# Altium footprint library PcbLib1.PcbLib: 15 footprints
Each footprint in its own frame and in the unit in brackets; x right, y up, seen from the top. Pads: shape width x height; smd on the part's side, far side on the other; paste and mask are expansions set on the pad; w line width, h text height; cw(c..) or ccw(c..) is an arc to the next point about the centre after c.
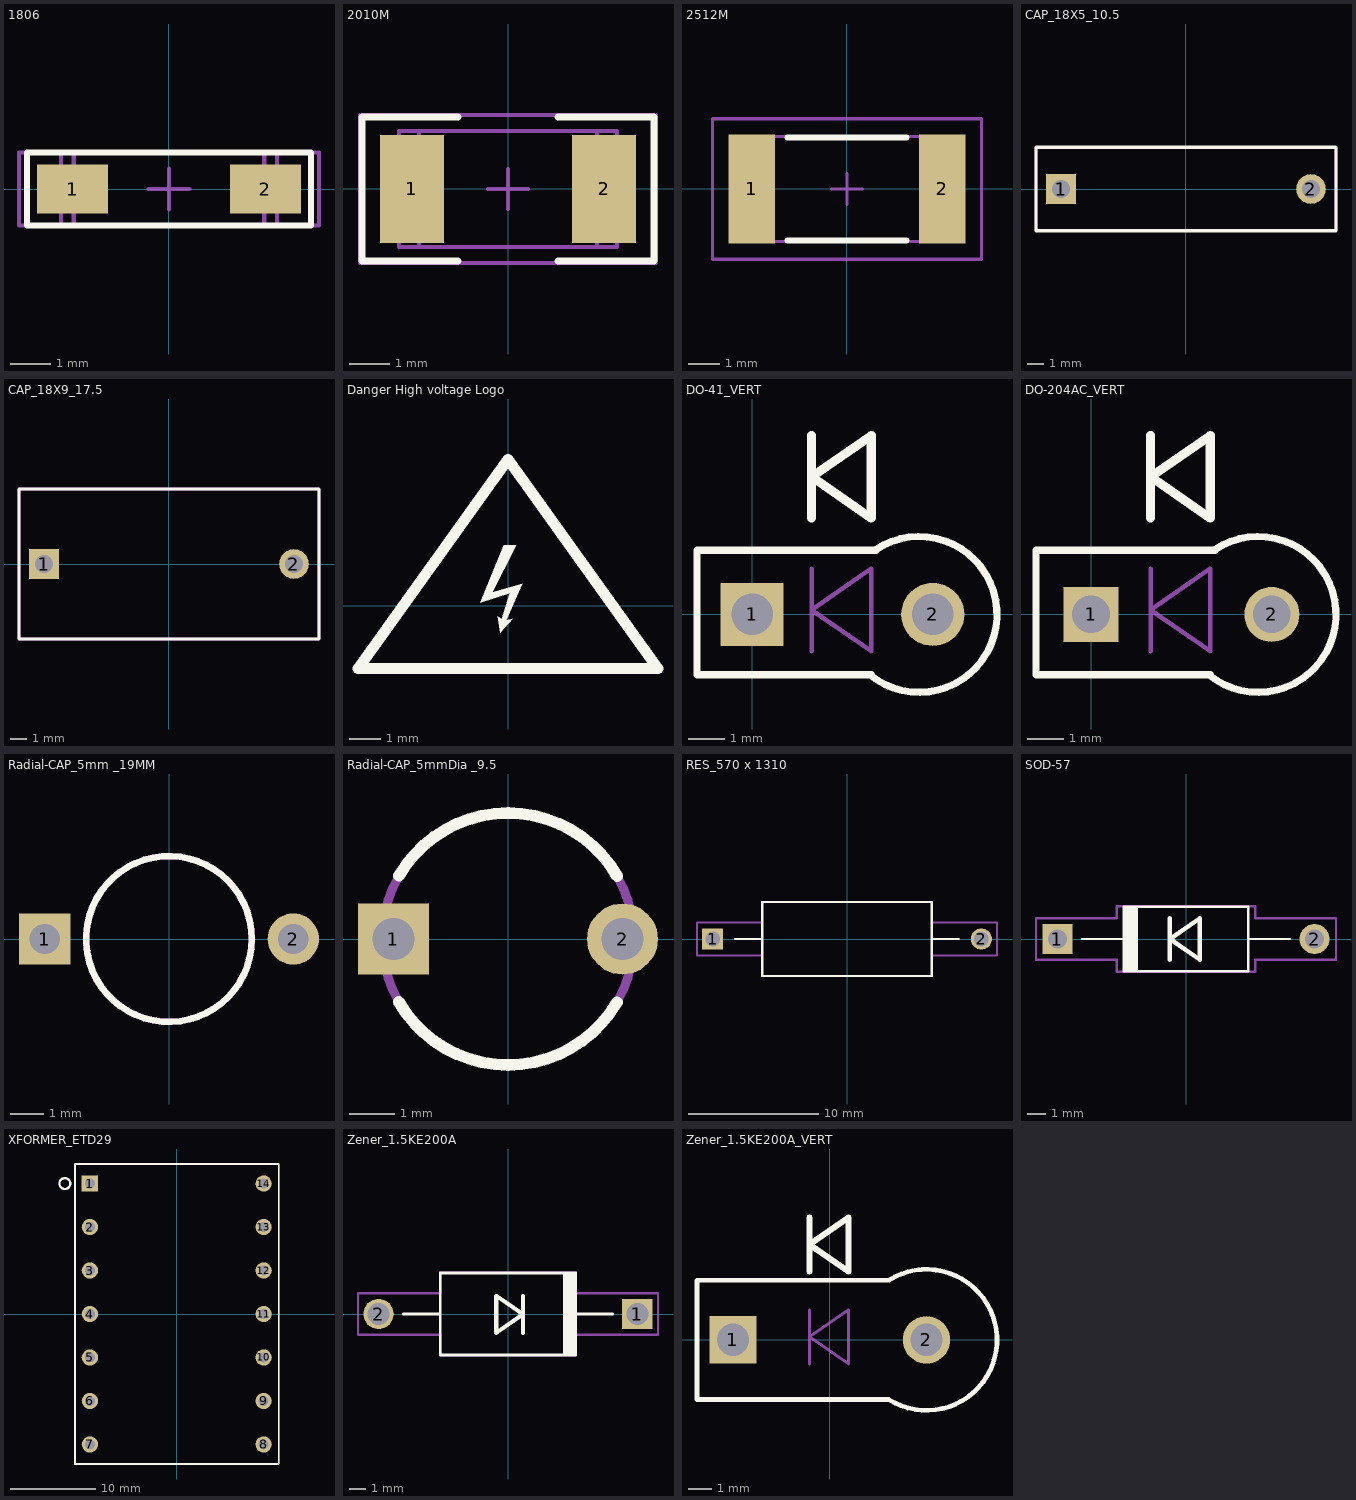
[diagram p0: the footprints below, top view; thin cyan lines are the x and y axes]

## 1806 [mm]
height 1.66
pads (2):
  rect 1.75x1.2 smd: 1(-2.375,0) 2(2.375,0)
Top Overlay:
  lines w0.152: -3.505,-0.9 3.505,-0.9 3.505,0.9 -3.505,0.9 -3.505,-0.9
Mechanical 5:
  lines w0.1: -2.35,-0.9 -2.35,0.9 ; -2.35,-0.9 2.35,-0.9 ; -2.35,-0.9 -2.667,-0.9 -2.667,0.9 -2.35,0.9 ; -2.35,0.9 2.35,0.9 ; 2.35,-0.9 2.35,0.9 ; 2.35,-0.9 2.667,-0.9 2.667,0.9 2.35,0.9
  text ".Designator" at -3.81,1.524 h1.02
Mechanical 15:
  lines w0.1: -0.5,0 0.5,0 ; 0,-0.5 0,0.5 ; -3.7,-0.9 3.7,-0.9 3.7,0.9 -3.7,0.9 -3.7,-0.9
3D body: height 1.6, standoff 0, extent -2.667,-0.9 2.667,0.9

## 2010M [mm]
height 1.66
pads (2):
  rect 1.6x2.7 smd: 1(-2.4,0) 2(2.4,0)
Top Overlay:
  lines w0.178: -1.25,-1.8 -3.65,-1.8 -3.65,1.8 -1.25,1.8 ; 1.25,-1.8 3.65,-1.8 3.65,1.8 1.25,1.8
Mechanical 5:
  lines w0.1: -2.73,-1.45 -2.73,1.45 2.73,1.45 2.73,-1.45 -2.73,-1.45
  text ".Designator" at -0.813,-0.508 h1.02
Mechanical 13:
  lines w0.1: -2.23,-1.45 -2.23,1.45 ; 2.23,-1.45 2.23,1.45 ; -2.73,-1.45 -2.73,1.45 2.73,1.45 2.73,-1.45 -2.73,-1.45
Mechanical 15:
  lines w0.1: -0.5,0 0.5,0 ; 0,-0.5 0,0.5 ; -3.7,-1.85 -3.7,1.85 3.7,1.85 3.7,-1.85 -3.7,-1.85
3D body: height 1.66, standoff 0, extent 2.231,-1.449 2.729,1.449
3D body: height 1.66, standoff 0, extent -2.229,-1.449 2.229,1.449
3D body: height 1.66, standoff 0, extent -2.729,-1.449 -2.231,1.449

## 2512M [mm] "Chip Resistor, Body 6.3x3.2mm, IPC Low Density"
height 0.71
pads (2):
  rect 1.5x3.5 smd: 1(-3.05,0) 2(3.05,0)
Top Overlay:
  lines w0.2: -1.9,-1.65 1.9,-1.65 ; -1.9,1.65 1.9,1.65
Mechanical 5:
  lines w0.1: -3.225,-1.675 3.225,-1.675 3.225,1.675 -3.225,1.675 -3.225,-1.675
  text ".Designator" at -0.711,-0.356 h1.02
Mechanical 13:
  lines w0.1: -2.463,-1.675 -2.463,1.675 ; 2.463,-1.675 2.463,1.675 ; -3.225,-1.675 3.225,-1.675 3.225,1.675 -3.225,1.675 -3.225,-1.675
Mechanical 15:
  lines w0.1: -0.5,0 0.5,0 ; 0,-0.5 0,0.5 ; -4.3,-2.25 4.3,-2.25 4.3,2.25 -4.3,2.25 -4.3,-2.25
3D body: height 0.71, standoff 0, extent -3.224,-1.674 -2.464,1.674
3D body: height 0.71, standoff 0, extent -2.462,-1.674 2.462,1.674
3D body: height 0.71, standoff 0, extent 2.464,-1.674 3.224,1.674

## CAP_18X5_10.5 [mil] "CAP FILM 2200PF 2KVDC RADIAL"
height 413.39
pads (2):
  rect 70x70 hole 42: 1(-295.27,0)
  round 70 hole 42: 2(295.28,0)
Top Overlay:
  lines w8: -354.33,-98.43 354.33,-98.43 354.33,98.42 -354.33,98.42 -354.33,-98.42
Mechanical 5:
  lines w6: -354.33,-98.43 -354.33,98.43 354.33,98.43 354.33,-98.43 -354.33,-98.43
  text ".Designator" at -180,-10 h40
3D body: height 393.7, standoff 39.37, extent -354.33,-98.43 354.33,98.43

## CAP_18X9_17.5 [mil] "CAP FILM 0.033UF 1.6KVDC RADIAL"
height 688.98
pads (2):
  rect 70x70 hole 42: 1(-295.27,0)
  round 70 hole 42: 2(295.28,0)
Top Overlay:
  lines w8: -354.33,-177.17 354.33,-177.17 354.33,177.17 -354.33,177.17 -354.33,-177.17
Mechanical 5:
  lines w6: -354.33,-177.17 354.33,-177.17 354.33,177.17 -354.33,177.17 -354.33,-177.17
  text ".Designator" at -180,-10 h40
3D body: height 688.98, standoff 39.37, extent -354.33,-177.17 354.33,177.17

## Danger High voltage Logo [mil]
Top Overlay:
  region: -5.07,76.5 10.63,76.5 -19.93,16.5 18.07,27.5 -1.93,-18.5 6.07,-16.5 -9.93,-34.5 -12.93,-13.5 -7.93,-17.5 2.07,15.5 -34.93,3.5
  lines w14: -190,-80 190,-80 0,185.17 -190,-80

## DO-41_VERT [mm]
pads (2):
  rect 1.75x1.75 hole 1.15: 1(0,0)
  round 1.75 hole 1.15: 2(5.01,0)
Top Overlay:
  lines w0.2: 3.262,-1.671 ccw(c4.629,0) 3.423,1.791 ; 3.302,-1.671 -1.524,-1.671 -1.524,1.778 3.429,1.778
  lines w0.254: 1.651,2.667 1.651,4.953 ; 1.651,3.81 3.302,4.953 3.302,2.667 1.651,3.81
Mechanical 5:
  lines w0.127: 1.651,-1.016 1.651,1.27 ; -1.524,-1.671 -1.524,1.791 3.423,1.791 cw(c4.629,0) 3.262,-1.671 -1.524,-1.671 ; 1.651,0.127 3.302,1.27 3.302,-1.016 1.651,0.127
  text ".Designator" at -2.448,-3.556 h1.02

## DO-204AC_VERT [mil]
pads (2):
  rect 60x60 hole 41: 1(0,0)
  round 60 hole 41: 2(197.24,0)
Top Overlay:
  lines w7.87: 128.44,-65.8 ccw(c182.24,0) 134.76,70.5 ; 130,-65.79 -60,-65.79 -60,70 135,70
  lines w10: 65,105 65,195 ; 65,150 130,195 130,105 65,150
Mechanical 5:
  lines w5: 65,-40 65,50 ; -60,-65.8 -60,70.5 134.76,70.5 cw(c182.24,0) 128.43,-65.8 -60,-65.8 ; 65,5 130,50 130,-40 65,5
  text ".Designator" at -96.38,-140 h40

## Radial-CAP_5mm _19MM [mil] "Radial, Disc,"
height 748.03
pads (2):
  rect 61x61 hole 36: 1(-147.64,0)
  round 61 hole 36: 2(147.64,0)
Top Overlay:
  circle w7.87: c0,0 r98.43
Mechanical 5:
  circle w7.87: c0,0 r98.43
  text ".Designator" at -175,65 h40
3D body: height 877.95, standoff 681.1, extent -97.39,-98 98.44,98.01

## Radial-CAP_5mmDia _9.5 [mil] "Radial, Disc,"
height 374.02
pads (2):
  rect 61x61 hole 36: 1(-98.43,0)
  round 61 hole 36: 2(98.43,0)
Top Overlay:
  lines w10: -93.76,-54.13 ccw(c0,0) 93.7,-54.25 ; -93.7,54.25 cw(c0,0) 93.76,54.13
Mechanical 5:
  circle w7.87: c0,0 r108.27
  text ".Designator" at -185,75 h40
3D body: height 374.02, standoff 0, extent -107.41,-108.05 108.28,108.06

## RES_570 x 1310 [mil] "Thick Film , AXIAL"
height 225
pads (2):
  rect 64x64 hole 44: 1(-407.5,0)
  round 64 hole 44: 2(407.5,0)
Top Overlay:
  lines w7: -340,0 -257.5,0 ; 257.5,0 340,0 ; -257.5,-112.5 -257.5,112.5 257.5,112.5 257.5,-112.5 -257.5,-112.5
Mechanical 5:
  lines w6: -455,-50 -257.5,-50 -257.5,-112.5 257.5,-112.5 257.5,-50 455,-50 455,50 257.5,50 257.5,112.5 -257.5,112.5 -257.5,50 -455,50 -455,-50
  text ".Designator" at -200,-5 h40
3D body: height 225, standoff 0, extent -455,-110 455,115

## SOD-57 [mil]
height 141.73
pads (2):
  rect 65x65 hole 42: 1(-278.5,0)
  round 65 hole 42: 2(278.5,0)
Top Overlay:
  region: -135,-70 -105,-70 -105,70 -135,70
  lines w5: -225,0 -135,0 ; 135,0 225,0 ; -135,-70 -135,70 135,70 135,-70 -135,-70
  lines w10: -35,-45 -35,45 ; -35,0 30,-45 30,45 -35,0
Mechanical 5:
  lines w5: -35,-45 -35,45 ; -325,-45 -150,-45 -150,-70.87 150,-70.87 150,-45 325,-45 325,45 150,45 150,70.87 -150,70.87 -150,45 -325,45 -325,-45 ; -35,0 30,-45 30,45 -35,0
  text ".Designator" at -180,-130 h40

## XFORMER_ETD29 [mil]
height 1535.43
pads (14):
  rect 75x75 hole 46: 1(-399.61,600)
  round 75 hole 46: 2(-399.61,400) 3(-399.61,200) 4(-399.61,0) 5(-399.61,-200) 6(-399.61,-400) 7(-399.61,-600) 8(399.61,-600) 9(399.61,-400) 10(399.61,-200) 11(399.61,0) 12(399.61,200) 13(399.61,400) 14(399.61,600)
Top Overlay:
  circle w10: c-515,600 r25
  lines w7.87: -468.5,-690 468.5,-690 468.5,690 -468.5,690 -468.5,-690
Mechanical 5:
  circle w10: c-515,600 r25
  lines w6: -468.5,-688.98 -468.5,688.98 468.5,688.98 468.5,-688.98 -468.5,-688.98
  text ".Designator" at -200,-10 h40
3D body: height 1535.43, standoff 0, extent -468.5,-688.98 468.5,688.98

## Zener_1.5KE200A [mil] "TVS DIODE, AXIAL"
height 208.66
pads (2):
  rect 74x74 hole 54: 1(315,0)
  round 74 hole 54: 2(-315,0)
Top Overlay:
  region: 165,100 135,100 135,-100 165,-100
  lines w7: -255,0 -165,0 ; 165,0 255,0 ; -165,-100 -165,100 165,100 165,-100 -165,-100
  lines w10: 36.5,-46.04 36.5,43.96 ; -28.5,-46.04 -28.5,43.96 36.5,-1.04 -28.5,-46.04
Mechanical 5:
  lines w6: -365,-50 -365,50 -165,50 -165,100 165,100 165,50 365,50 365,-50 165,-50 165,-100 -165,-100 -165,-50 -365,-50
  text ".Designator" at -195,135 h40
3D body: height 200, standoff 0, extent -365,-100 365,100

## Zener_1.5KE200A_VERT [mil]
pads (2):
  rect 79x79 hole 54: 1(-161.42,0)
  round 79 hole 54: 2(161.42,0)
Top Overlay:
  lines w7.87: -221.42,-99.41 98.43,-99.41 ccw(c161.42,0) 98.43,99.41 -221.42,99.41 -221.42,-99.41
  lines w10: -33.62,114.05 -33.62,204.05 ; -33.62,159.05 31.38,114.05 31.38,204.05 -33.62,159.05
Mechanical 5:
  lines w5: -33.62,-40 -33.62,50 ; -33.62,5 31.38,-40 31.38,50 -33.62,5
  text ".Designator" at -195,-165 h40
